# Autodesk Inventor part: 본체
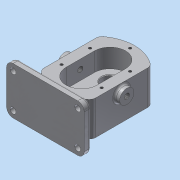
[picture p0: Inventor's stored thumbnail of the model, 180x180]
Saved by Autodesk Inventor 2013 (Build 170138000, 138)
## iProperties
Created: 2019-03
Part Number: 본체
Material: 알루미늄 6061
Document SubType Name: Modeling
Designer: dgall
Density: 2.71 g/cm^3
Mass: 1193.31 g
Surface Area: 723.859 cm^2
Volume: 440.336 cm^3
Author: dgall
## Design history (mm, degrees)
sketch "스케치2"
  geometry: L1 (-40, 44.721)-(-40, -44.721); L2 (40, 44.721)-(40, -44.721); A1 r 60 centre (0, 0) between (40, 44.721) and (-40, 44.721); A2 r 60 centre (0, 0) between (-40, -44.721) and (40, -44.721); 1 further point
  constraints: 4 end point, 4 point on circle, 2 centre point, 2 coincident, 1 horizontal alignment, 1 parallel, 1 vertical
  dimensions: "d7" = 60 radius of A1; "d8" = 60 radius of A2; "d9" = 80 distance between parallel lines of L2 L1
extrude "돌출2" new body sketch "스케치2" stored distance "d10" = 53; taper "d11" = 0 deg
sketch "스케치3"
  geometry: L1 (-24, 22)-(-24, -22); L2 (24, 22)-(24, -22); A1 r 60 centre (0, 0) between (40, 44.721) and (-40, 44.721) reference; A2 r 24 centre (0, 22) between (24, 22) and (-24, 22); A3 r 24 centre (0, -22) between (-24, -22) and (24, -22); 1 further point
  constraints: 4 end point, 4 point on circle, 4 tangent, 2 centre point, 2 vertical alignment, 1 equal radius, 1 horizontal alignment, 1 midpoint
  dimensions: "d13" = 44 distance of A3.centre A2.centre; "d14" = 24 radius of A2
extrude "돌출3" cut sketch "스케치3" distance "d15" = 29; taper "d16" = 0 deg
sketch "스케치4"
  geometry: A1 r 24 centre (0, 22) between (24, 22) and (-24, 22) reference; 2 further points
  constraints: 1 coincident
hole "구멍1" sketch "스케치4" at (0, 22) diameter "d17" = 17; stored, may be unused: countersink angle "d21" = 90 deg, drill point angle "d23" = 118 deg; dims "d18" = 6, "d19" = 25, "d20" = 15, "d22" = 8
sketch "스케치5"
  geometry: C1 r 12.5 at (0, -22); A1 r 24 centre (0, -22) between (-24, -22) and (24, -22) reference; 1 further point
  constraints: 1 centre point, 1 coincident
  dimensions: "d24" = 25 diameter of C1
extrude "돌출4" cut sketch "스케치5" distance "d25" = 15; taper "d26" = 0 deg
sketch "스케치6"
  geometry: C1 r 8.5 at (0, 22) reference; C2 r 19 at (0, 22)
  constraints: 1 centre point, 1 coincident
  dimensions: "d27" = 38 diameter of C2
extrude "돌출5" join sketch "스케치6" distance "d28" = 17; taper "d29" = 0 deg
sketch "스케치9"
  geometry: L1 (0, 0)-(0, 89.443) reference; L2 (70, 47.721)-(70, 85.721) reference; C1 r 11 at (14, 44.721); 2 further points
  constraints: 1 centre point, 1 midpoint
  dimensions: "d36" = 22 diameter of C1; "d37" = 22 vertical distance of point (70, 66.721) C1.centre; "d38" = 14 distance from line of L1 C1.centre
extrude "돌출6" join sketch "스케치9" distance "d39" = 8; taper "d40" = 0 deg
hole "구멍2" diameter "d43" = 8.376; stored, may be unused: countersink angle "d47" = 90 deg, drill point angle "d49" = 118 deg; dims "d41" = 10, "d42" = 10, "d44" = 6, "d45" = 25, "d46" = 15, "d48" = 8
node "작업 평면1"
sketch "스케치10"
  geometry: L1 (60, 46.5)-(-60, 46.5); L2 (-60, 46.5)-(-60, -26.5); L3 (-60, -26.5)-(60, -26.5); L4 (60, -26.5)-(60, 46.5); L5 (-19, -43.5)-(19, -43.5) reference; 2 further points
  constraints: 8 end point, 2 parallel, 1 horizontal, 1 midpoint, 1 perpendicular, 1 vertical alignment
  dimensions: "d51" = 73 distance of L3.end L1.start; "d53" = 120 distance of L2.end L3.end; "d54" = 90 distance between parallel lines of L5 L1
extrude "돌출7" join sketch "스케치10" distance "d55" = 10; taper "d56" = 0 deg
fillet "모깎기3" dims "d60" = 10
sketch "스케치12"
  geometry: L1 (50, 26.5)-(-50, 26.5) reference; L2 (60, 16.5)-(60, -36.5) reference; L3 (50, -46.5)-(-50, -46.5) reference; L4 (-60, -36.5)-(-60, 16.5) reference; L5 (-50, 26.5)-(50, 26.5) reference; L6 (60, 16.5)-(60, -36.5) reference; L7 (50, -46.5)-(-50, -46.5) reference; L8 (-60, -36.5)-(-60, 16.5) reference; L9 (-50, 26.5)-(50, 26.5) reference; L10 (60, 16.5)-(60, -36.5) reference; L11 (50, -46.5)-(-50, -46.5) reference; L12 (-60, -36.5)-(-60, 16.5) reference; L13 (-50, 26.5)-(50, 26.5) reference; L14 (-6, 26.5)-(-6, -16.5); L15 (-6, -16.5)-(6, -16.5); L16 (6, -16.5)-(6, 26.5); A1 r 10 centre (50, 16.5) between (60, 16.5) and (50, 26.5) reference; A2 r 10 centre (50, -36.5) between (50, -46.5) and (60, -36.5) reference; A3 r 10 centre (-50, -36.5) between (-60, -36.5) and (-50, -46.5) reference; A4 r 10 centre (-50, 16.5) between (-50, 26.5) and (-60, 16.5) reference; A5 r 10 centre (50, 16.5) between (60, 16.5) and (50, 26.5) reference; A6 r 10 centre (50, -36.5) between (50, -46.5) and (60, -36.5) reference; A7 r 10 centre (-50, -36.5) between (-60, -36.5) and (-50, -46.5) reference; A8 r 10 centre (-50, 16.5) between (-50, 26.5) and (-60, 16.5) reference; A9 r 10 centre (50, 16.5) between (60, 16.5) and (50, 26.5) reference; A10 r 10 centre (50, -36.5) between (50, -46.5) and (60, -36.5) reference; A11 r 10 centre (-50, -36.5) between (-60, -36.5) and (-50, -46.5) reference; A12 r 10 centre (-50, 16.5) between (-50, 26.5) and (-60, 16.5) reference; 3 further points
  constraints: 6 end point, 2 midpoint, 2 perpendicular, 2 point on line, 1 parallel, 1 vertical alignment
  dimensions: "d61" = 12 distance of L14.end L15.end; "d63" = 43 distance of L15.end L16.end
extrude "돌출9" join sketch "스케치12" stored distance "d64" = 12; taper "d65" = 0 deg
fillet "모깎기10" dims "d72" = 3
fillet "모깎기11" dims "d73" = 3
fillet "모깎기12" dims "d74" = 3
fillet "모깎기13" dims "d75" = 3
fillet "모깎기14" dims "d76" = 3
hole "구멍3" diameter "d79" = 9; stored, may be unused: countersink angle "d83" = 90 deg, drill point angle "d85" = 118 deg; dims "d77" = 10, "d78" = 10, "d80" = 6, "d81" = 25, "d82" = 15, "d84" = 8
sketch "스케치15"
  geometry: A1 r 24 centre (0, -22) between (-24, -22) and (24, -22) reference; A2 r 24 centre (0, 22) between (24, 22) and (-24, 22) reference; A3 r 60 centre (0, 0) between (40, 44.721) and (-40, 44.721) reference; 6 further points
  constraints: 4 horizontal alignment, 2 vertical alignment
  dimensions: "d112" = 106 distance of point (0, -53) point (0, 53); "d114" = 53 distance of A3.centre point (0, 53); "d115" = 31 distance of A2.centre point (-31, 22); "d116" = 31 distance of point (-31, -22) A1.centre; "d117" = 62 distance of point (31, 22) point (-31, 22); "d118" = 62 distance of point (-31, -22) point (31, -22)
hole "구멍6" sketch "스케치15" at (0, 53), (0, -53), (-31, 22), (31, 22), (31, -22), (-31, -22) diameter "d119" = 4.134; stored, may be unused: countersink angle "d123" = 90 deg, drill point angle "d125" = 118 deg; dims "d120" = 10, "d121" = 25, "d122" = 15, "d124" = 12
fillet "모깎기15" dims "d126" = 3
fillet "모깎기16" dims "d127" = 10
fillet "모깎기17" dims "d128" = 3
chamfer "모따기2" distance "d133" = 1; stored, may be unused: second distance "d134" = 2, angle "d135" = 45 deg
chamfer "모따기3" distance "d136" = 1; stored, may be unused: second distance "d137" = 2, angle "d138" = 45 deg
sketch "스케치16"
  geometry: L1 (-60, 16.5)-(-60, -36.5) reference; L2 (-50, -46.5)-(50, -46.5) reference; 2 further points
  constraints: 1 other
  dimensions: "d139" = 60 distance from line of L1 point (0, -36.5); "d140" = 10 distance from line of L2 point (0, -36.5)
feature "엠보싱1" sketch "스케치16" dims "d141" = 0.5, "d142" = 0
sketch "스케치17"
  geometry: C1 r 19 at (0, 0) reference; C2 r 8.5 at (0, 0); 1 further point
  constraints: 1 centre point, 1 coincident
  dimensions: "d144" = 17 diameter of C2
extrude "돌출10" cut sketch "스케치17" stored distance "d146" = 10; taper "d147" = 0 deg
sketch "스케치22"
  geometry: L1 (53, 13.258)-(55.067, 14.5) reference; L2 (55.067, 14.5)-(55.067, 26.5) reference; L3 (55.067, 26.5)-(60, 26.5) reference; L4 (60, 26.5)-(60, -26.5) reference; L5 (60, -26.5)-(44, -26.5) reference; L6 (41, -29.5)-(41, -43.5) reference; L7 (41, -43.5)-(30.5, -43.5) reference; L8 (30.5, -43.5)-(30.5, -17.5) reference; L9 (30.5, -17.5)-(34.5, -17.5) reference; L10 (34.5, -17.5)-(34.5, -3.5) reference; L11 (34.5, -3.5)-(35.5, -2.5) reference; L12 (35.5, -2.5)-(46, -2.5) reference; L13 (46, -2.5)-(46, 26.5) reference; L14 (46, 26.5)-(50.933, 26.5) reference; L15 (50.933, 26.5)-(50.933, 14.5) reference; L16 (50.933, 14.5)-(53, 13.258) reference; L17 (-60, 19.5)-(-60, 26.5) reference; L18 (-60, 26.5)-(-55.067, 26.5) reference; L19 (-55.067, 26.5)-(-55.067, 14.5) reference; L20 (-55.067, 14.5)-(-53, 13.258) reference; L21 (-53, 13.258)-(-50.933, 14.5) reference; L22 (-50.933, 14.5)-(-50.933, 26.5) reference; L23 (-50.933, 26.5)-(-46, 26.5) reference; L24 (-46, 26.5)-(-46, -2.5) reference; L25 (-46, -2.5)-(-35.5, -2.5) reference; L26 (-35.5, -2.5)-(-34.5, -3.5) reference; L27 (-34.5, -3.5)-(-34.5, -17.5) reference; L28 (-34.5, -17.5)-(-9.5, -17.5) reference; L29 (-9.5, -17.5)-(-9.5, -3.5) reference; L30 (-9.5, -3.5)-(-8.5, -2.5) reference; L31 (-8.5, -2.5)-(8.5, -2.5) reference; L32 (8.5, -2.5)-(9.5, -3.5) reference; L33 (9.5, -3.5)-(9.5, -17.5) reference; L34 (9.5, -17.5)-(13.5, -17.5) reference; L35 (13.5, -17.5)-(13.5, -43.5) reference; L36 (13.5, -43.5)-(3, -43.5) reference; L37 (3, -43.5)-(3, -29.5) reference; L38 (0, -26.5)-(-78, -26.5) reference; L39 (-78, -26.5)-(-78, 46.5) reference; L40 (-78, 46.5)-(-71, 46.5) reference; L41 (-68, 43.5)-(-68, 34.529) reference; L42 (-68, 34.529)-(-67.5, 34.529) reference; L43 (-67.5, 34.529)-(-67.5, 34.115) reference; L44 (-67.5, 34.115)-(-68, 34.115) reference; L45 (-68, 34.115)-(-68, 19.5) reference; L46 (-65, 16.5)-(-63, 16.5) reference; L47 (36, -42.8)-(36, -36.2); L48 (30.5, -17.5)-(13.5, -17.5); L49 (22, -17.5)-(22, -43.5); L50 (36, -36.2)-(22, -36.2); L51 (36, -42.8)-(36.421, -43.5); L52 (30.5, -43.5)-(13.5, -43.5) reference; L53 (36.421, -43.5)-(22, -43.5); A1 r 3 centre (44, -29.5) between (44, -26.5) and (41, -29.5) reference; A2 r 3 centre (-63, 19.5) between (-63, 16.5) and (-60, 19.5) reference; A3 r 3 centre (0, -29.5) between (3, -29.5) and (0, -26.5) reference; A4 r 3 centre (-71, 43.5) between (-68, 43.5) and (-71, 46.5) reference; A5 r 3 centre (-65, 19.5) between (-68, 19.5) and (-65, 16.5) reference; 1 further point
  constraints: 12 end point, 3 perpendicular, 2 point on line, 1 collinear, 1 midpoint, 1 parallel, 1 vertical
  dimensions: "d161" = 28 diameter of L47 L49; "d162" = 0.7 vertical distance of L51.end L47.start; "d163" = 7.3 vertical distance of L47.end L51.end
revolve "회전3" sketch "스케치22" stored, may be unused: angle "d164" = 90 deg
node "솔리드2"
mirror "대칭1"
pattern_linear "직사각형 패턴1" dims "d88" = 100, "d91" = 53
node "절단 모서리 투영3"
node "절단 모서리 투영4"
node "절단 모서리 투영5"
node "절단 모서리 투영9"
other parameters: "d12" = 24, "d50" = -78
